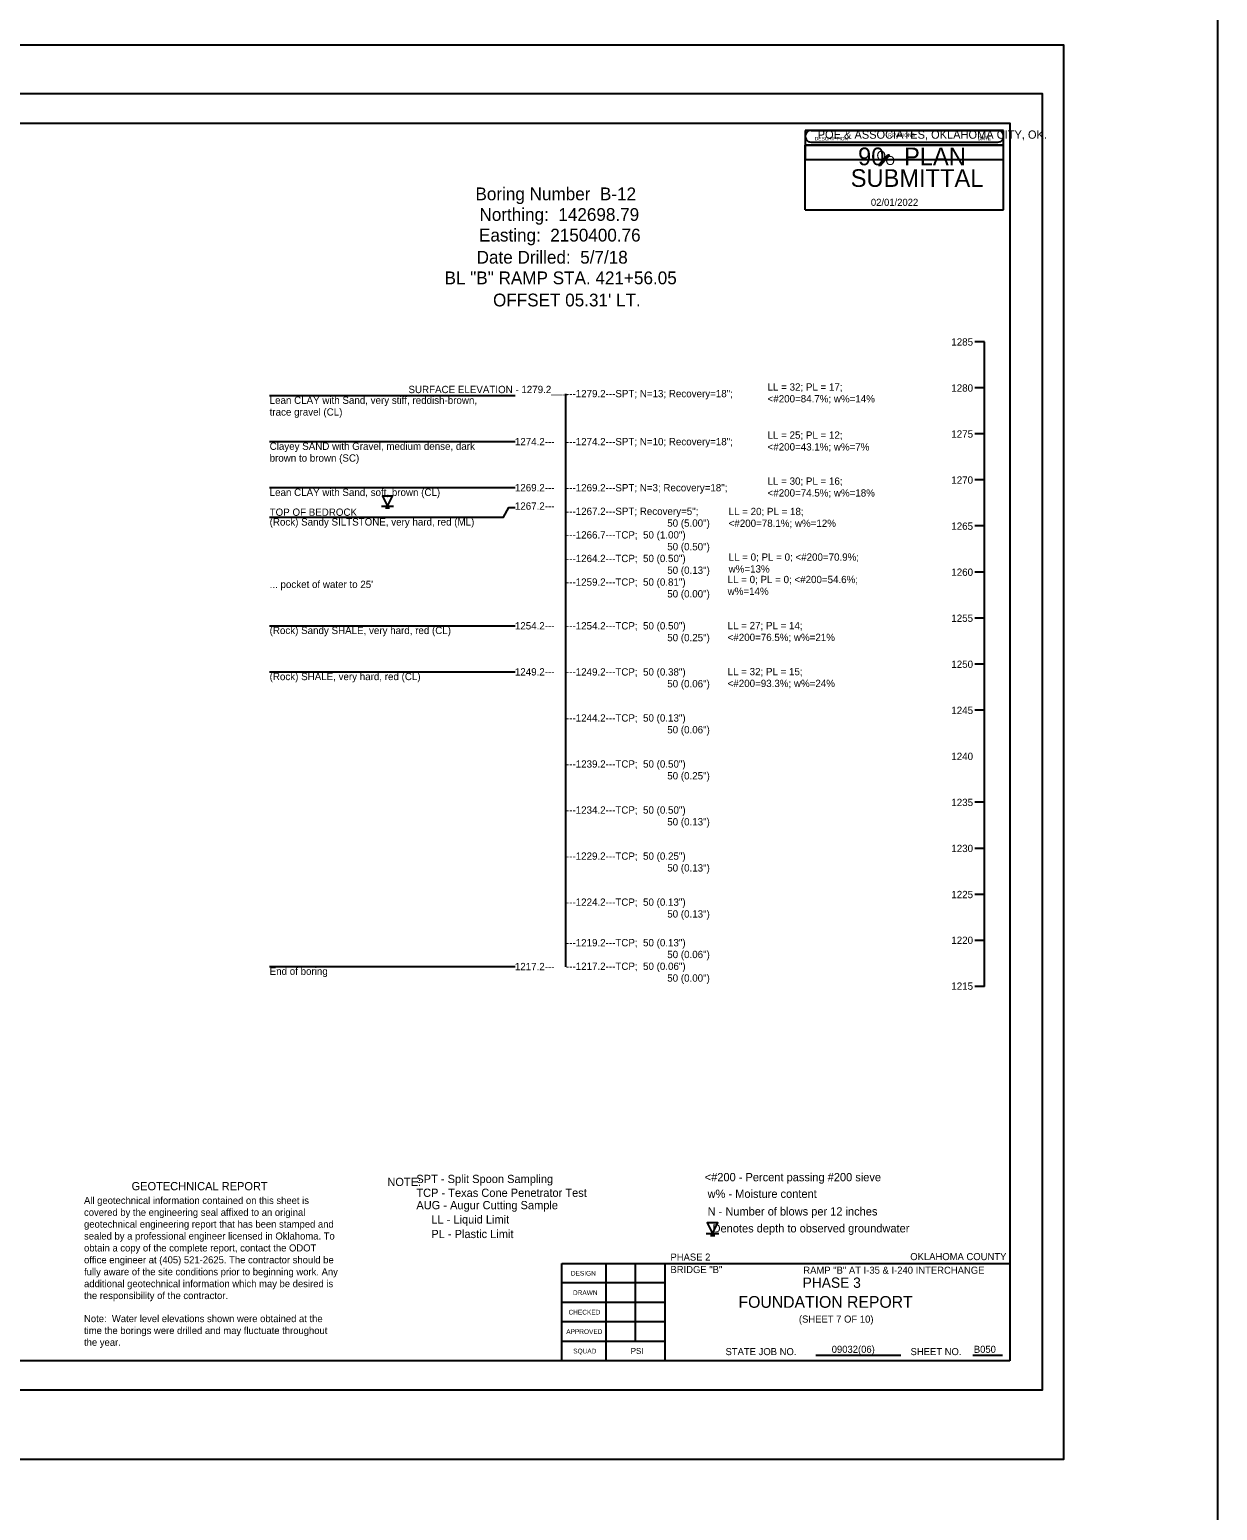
# Model space of a CAD drawing. Extents: x 2150162 to 2150245, y 143729 to 143865.
# Drawn here: x 2150225.08 to 2150245.24, y 143810.76 to 143835.89 of the extents above; entities that cross this region are included whole.
import ezdxf

# ---------------------------------------------------------------- set-up
doc = ezdxf.new("R2010")
doc.units = 0
for name, color, linetype in [('Default', 7, 'Continuous'), ('S', 7, 'Continuous'), ('SHT_Plot_Shape_Full', 7, 'Continuous'), ('SHT_Plot_Shape_Half', 7, 'Continuous'), ('SHT_Sheet_Border', 7, 'Continuous'), ('SHT_Stamp_90_Submit', 7, 'Continuous'), ('SHT_Stamp_Rev_Block', 7, 'Continuous'), ('SHT_Standard_Sheet_Lines', 7, 'Continuous'), ('SHT_Standard_Sheet_Txt', 7, 'Continuous'), ('T', 7, 'Continuous'), ('T-Title', 7, 'Continuous'), ('Text', 7, 'Continuous')]:
    doc.layers.add(name, color=color, linetype=linetype)

# ---------------------------------------------------------------- blocks, each defined once
blk = doc.blocks.new('DGRFC_WTLEV1')
at = {"layer": 'Default'}
for points in [[(-0.0127, 0), (0.0127, 0)], [(0, 0), (0.0106, 0.0212), (-0.0106, 0.0212), (0, 0)], [(-0.0042, -0.0042), (0.0042, -0.0042)]]:
    blk.add_lwpolyline(points, dxfattribs=at)

msp = doc.modelspace()

# ---------------------------------------------------------------- linework, layer by layer
at = {"layer": 'Default'}
msp.add_line((2150241.288, 143819.651), (2150241.288, 143830.588), dxfattribs=at)
for points in [[(2150241.288, 143830.59), (2150241.121, 143830.59)], [(2150229.155, 143829.677), (2150233.322, 143829.677)], [(2150234.174, 143829.705), (2150234.174, 143819.982)], [(2150241.288, 143829.808), (2150241.121, 143829.808)], [(2150229.155, 143828.895), (2150233.322, 143828.895)], [(2150234.174, 143828.845), (2150234.174, 143823.374)], [(2150241.288, 143829.027), (2150241.121, 143829.027)], [(2150241.288, 143829.027), (2150241.121, 143829.027)], [(2150229.155, 143828.114), (2150233.322, 143828.114)], [(2150241.288, 143828.246), (2150241.121, 143828.246)], [(2150229.155, 143827.611), (2150233.124, 143827.611), (2150233.213, 143827.777), (2150233.322, 143827.777)], [(2150241.288, 143827.465), (2150241.121, 143827.465)], [(2150241.288, 143826.683), (2150241.121, 143826.683)], [(2150241.288, 143825.902), (2150241.121, 143825.902)], [(2150229.155, 143825.77), (2150233.322, 143825.77)], [(2150241.288, 143825.121), (2150241.121, 143825.121)], [(2150229.155, 143824.989), (2150233.322, 143824.989)], [(2150241.288, 143824.34), (2150241.121, 143824.34)], [(2150241.288, 143822.776), (2150241.121, 143822.776)], [(2150241.288, 143821.994), (2150241.121, 143821.994)], [(2150241.288, 143821.213), (2150241.121, 143821.213)], [(2150241.288, 143820.432), (2150241.121, 143820.432)], [(2150229.155, 143819.989), (2150233.322, 143819.989)], [(2150241.288, 143819.651), (2150241.121, 143819.651)]]:
    msp.add_lwpolyline(points, dxfattribs=at)
at = {"layer": 'S'}
msp.add_lwpolyline([(2150203.404, 143865.061), (2150245.24, 143865.061), (2150245.24, 143729.315), (2150203.404, 143729.315)], close=True, dxfattribs=at)
at = {"layer": 'SHT_Plot_Shape_Full'}
msp.add_lwpolyline([(2150206.628, 143835.625), (2150242.628, 143835.625), (2150242.628, 143811.625), (2150206.628, 143811.625)], close=True, dxfattribs=at)
at = {"layer": 'SHT_Plot_Shape_Half'}
msp.add_lwpolyline([(2150208.265, 143834.8), (2150242.265, 143834.8), (2150242.265, 143812.8), (2150208.265, 143812.8)], close=True, dxfattribs=at)
at = {"layer": 'SHT_Sheet_Border'}
for p, q in [((2150234.115, 143813.3), (2150234.115, 143814.95)), ((2150234.115, 143814.95), (2150241.715, 143814.95)), ((2150235.865, 143813.3), (2150235.865, 143814.951))]:
    msp.add_line(p, q, dxfattribs=at)
msp.add_lwpolyline([(2150241.715, 143813.3), (2150210.215, 143813.3), (2150210.215, 143834.3), (2150241.715, 143834.3)], close=True, dxfattribs=at)
at = {"layer": 'SHT_Stamp_90_Submit'}
for p, q in [((2150238.346, 143834.176), (2150241.512, 143834.176)), ((2150238.246, 143833.926), (2150241.612, 143833.926)), ((2150238.246, 143832.827), (2150238.246, 143833.926)), ((2150238.346, 143833.976), (2150241.512, 143833.976)), ((2150241.612, 143832.827), (2150241.612, 143833.926)), ((2150239.489, 143833.588), (2150239.645, 143833.76)), ((2150239.507, 143833.588), (2150239.662, 143833.76)), ((2150239.512, 143833.588), (2150239.667, 143833.76)), ((2150239.52, 143833.588), (2150239.675, 143833.76)), ((2150239.645, 143833.76), (2150239.675, 143833.76)), ((2150239.489, 143833.588), (2150239.52, 143833.588)), ((2150238.246, 143832.827), (2150241.612, 143832.827))]:
    msp.add_line(p, q, dxfattribs=at)
for centre, start, end in [((2150238.346, 143834.076), 89.9952, 270), ((2150241.512, 143834.076), 270, 90.0048)]:
    msp.add_arc(centre, 0.1, start, end, dxfattribs=at)
at = {"layer": 'SHT_Stamp_Rev_Block'}
for p, q in [((2150238.246, 143834.176), (2150238.246, 143833.676)), ((2150241.612, 143834.176), (2150238.246, 143834.176)), ((2150241.612, 143833.676), (2150241.612, 143834.176)), ((2150241.612, 143833.926), (2150238.246, 143833.926)), ((2150241.612, 143833.676), (2150238.246, 143833.676))]:
    msp.add_line(p, q, dxfattribs=at)
at = {"layer": 'SHT_Standard_Sheet_Lines'}
for p, q in [((2150234.865, 143813.3), (2150234.865, 143814.951)), ((2150235.365, 143813.63), (2150235.365, 143814.951)), ((2150238.426, 143813.396), (2150239.866, 143813.396)), ((2150241.09, 143813.396), (2150241.593, 143813.396))]:
    msp.add_line(p, q, dxfattribs=at)
for points in [[(2150235.865, 143814.62), (2150234.115, 143814.62)], [(2150235.865, 143814.29), (2150234.115, 143814.29)], [(2150235.865, 143813.96), (2150234.115, 143813.96)], [(2150235.865, 143813.63), (2150234.115, 143813.63)]]:
    msp.add_lwpolyline(points, dxfattribs=at)

# ---------------------------------------------------------------- block references
at = {"layer": 'Default'}
for p, xscale, yscale in [((2150231.155, 143827.802), 7.873999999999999, 7.873999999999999), ((2150236.672, 143815.46), 8.503919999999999, 8.503919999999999)]:
    msp.add_blockref('DGRFC_WTLEV1', p, dxfattribs=dict(at, xscale=xscale, yscale=yscale))

# ---------------------------------------------------------------- texts
for s, height, p in [('Boring Number  B-12', 0.217, (2150232.648, 143832.99)), ('Northing:  142698.79', 0.217, (2150232.716, 143832.64)), ('Easting:  2150400.76', 0.217, (2150232.708, 143832.29)), ('Date Drilled:  5/7/18', 0.217, (2150232.668, 143831.915)), ('BL "B" RAMP STA. 421+56.05', 0.217, (2150232.124, 143831.565)), ("OFFSET 05.31' LT.", 0.217, (2150232.946, 143831.189)), ('1285', 0.124, (2150240.724, 143830.524)), ('SURFACE ELEVATION - 1279.2___', 0.124, (2150231.511, 143829.718)), ('LL = 32; PL = 17;', 0.124, (2150237.606, 143829.76)), ('1280', 0.124, (2150240.724, 143829.743)), ('Lean CLAY with Sand, very stiff, reddish-brown,', 0.124, (2150229.155, 143829.536)), ('---1279.2---SPT; N=13; Recovery=18";', 0.124, (2150234.184, 143829.648)), ('<#200=84.7%; w%=14%', 0.124, (2150237.606, 143829.56)), ('trace gravel (CL)', 0.124, (2150229.155, 143829.336)), ('1275', 0.124, (2150240.724, 143828.962)), ('Clayey SAND with Gravel, medium dense, dark', 0.124, (2150229.155, 143828.755)), ('1274.2---', 0.124, (2150233.317, 143828.833)), ('---1274.2---SPT; N=10; Recovery=18";', 0.124, (2150234.184, 143828.833)), ('<#200=43.1%; w%=7%', 0.124, (2150237.606, 143828.744)), ('LL = 25; PL = 12;', 0.124, (2150237.606, 143828.944)), ('brown to brown (SC)', 0.124, (2150229.155, 143828.555)), ('Lean CLAY with Sand, soft, brown (CL)', 0.124, (2150229.155, 143827.973)), ('1269.2---', 0.124, (2150233.317, 143828.052)), ('---1269.2---SPT; N=3; Recovery=18";', 0.124, (2150234.184, 143828.051)), ('<#200=74.5%; w%=18%', 0.124, (2150237.606, 143827.963)), ('LL = 30; PL = 16;', 0.124, (2150237.606, 143828.163)), ('1270', 0.124, (2150240.724, 143828.181)), ('1267.2---', 0.124, (2150233.317, 143827.74)), ('TOP OF BEDROCK', 0.124, (2150229.155, 143827.636)), ('(Rock) Sandy SILTSTONE, very hard, red (ML)', 0.124, (2150229.155, 143827.471)), ('---1267.2---SPT; Recovery=5";', 0.124, (2150234.184, 143827.651)), ('50 (5.00")', 0.124, (2150235.903, 143827.451)), ('<#200=78.1%; w%=12%', 0.124, (2150236.945, 143827.448)), ('LL = 20; PL = 18;', 0.124, (2150236.945, 143827.648)), ('---1266.7---TCP;  50 (1.00")', 0.124, (2150234.184, 143827.251)), ('1265', 0.124, (2150240.724, 143827.399)), ('50 (0.50")', 0.124, (2150235.903, 143827.051)), ('---1264.2---TCP;  50 (0.50")', 0.124, (2150234.184, 143826.851)), ('LL = 0; PL = 0; <#200=70.9%;', 0.124, (2150236.945, 143826.874)), ('---1259.2---TCP;  50 (0.81")', 0.124, (2150234.184, 143826.451)), ('50 (0.13")', 0.124, (2150235.903, 143826.651)), ('LL = 0; PL = 0; <#200=54.6%;', 0.124, (2150236.928, 143826.494)), ('w%=13%', 0.124, (2150236.945, 143826.674)), ('1260', 0.124, (2150240.724, 143826.618)), ("... pocket of water to 25'", 0.124, (2150229.155, 143826.411)), ('50 (0.00")', 0.124, (2150235.903, 143826.251)), ('w%=14%', 0.124, (2150236.928, 143826.294)), ('1254.2---', 0.124, (2150233.317, 143825.708)), ('---1254.2---TCP;  50 (0.50")', 0.124, (2150234.184, 143825.708)), ('LL = 27; PL = 14;', 0.124, (2150236.928, 143825.712)), ('1255', 0.124, (2150240.724, 143825.837)), ('(Rock) Sandy SHALE, very hard, red (CL)', 0.124, (2150229.155, 143825.63)), ('50 (0.25")', 0.124, (2150235.903, 143825.508)), ('<#200=76.5%; w%=21%', 0.124, (2150236.928, 143825.512)), ('---1249.2---TCP;  50 (0.38")', 0.124, (2150234.184, 143824.926)), ('LL = 32; PL = 15;', 0.124, (2150236.928, 143824.931)), ('1250', 0.124, (2150240.724, 143825.056)), ('(Rock) SHALE, very hard, red (CL)', 0.124, (2150229.155, 143824.848)), ('1249.2---', 0.124, (2150233.317, 143824.927)), ('50 (0.06")', 0.124, (2150235.903, 143824.726)), ('<#200=93.3%; w%=24%', 0.124, (2150236.928, 143824.731)), ('1245', 0.124, (2150240.724, 143824.274)), ('---1244.2---TCP;  50 (0.13")', 0.124, (2150234.184, 143824.145)), ('50 (0.06")', 0.124, (2150235.903, 143823.945)), ('1240', 0.124, (2150240.724, 143823.493)), ('---1239.2---TCP;  50 (0.50")', 0.124, (2150234.184, 143823.364)), ('50 (0.25")', 0.124, (2150235.903, 143823.164)), ('1235', 0.124, (2150240.724, 143822.712)), ('---1234.2---TCP;  50 (0.50")', 0.124, (2150234.184, 143822.583)), ('50 (0.13")', 0.124, (2150235.903, 143822.383)), ('1230', 0.124, (2150240.724, 143821.931)), ('---1229.2---TCP;  50 (0.25")', 0.124, (2150234.184, 143821.801)), ('50 (0.13")', 0.124, (2150235.903, 143821.601)), ('---1224.2---TCP;  50 (0.13")', 0.124, (2150234.184, 143821.02)), ('1225', 0.124, (2150240.724, 143821.149)), ('50 (0.13")', 0.124, (2150235.903, 143820.82)), ('---1219.2---TCP;  50 (0.13")', 0.124, (2150234.184, 143820.332)), ('1220', 0.124, (2150240.724, 143820.373)), ('1217.2---', 0.124, (2150233.317, 143819.927)), ('---1217.2---TCP;  50 (0.06")', 0.124, (2150234.184, 143819.932)), ('50 (0.06")', 0.124, (2150235.903, 143820.132)), ('End of boring', 0.124, (2150229.155, 143819.848)), ('50 (0.00")', 0.124, (2150235.903, 143819.732)), ('1215', 0.124, (2150240.724, 143819.595))]:
    msp.add_text(s, height=height, dxfattribs=at).set_placement(p)
at = {"layer": 'Defpoints'}
msp.add_text('PHASE 3', height=0.175, dxfattribs=at).set_placement((2150238.2, 143814.538))
at = {"layer": 'SHT_Stamp_90_Submit'}
for s, height, p in [('POE & ASSOCIATES, OKLAHOMA CITY, OK.', 0.14, (2150238.456, 143834.034)), ('90   PLAN', 0.3, (2150239.141, 143833.584)), ('O', 0.153, (2150239.455, 143833.673)), ('O', 0.153, (2150239.607, 143833.588)), ('SUBMITTAL', 0.3, (2150239.017, 143833.217)), ('02/01/2022', 0.12, (2150239.359, 143832.895))]:
    msp.add_text(s, height=height, dxfattribs=at).set_placement(p)
at = {"layer": 'SHT_Stamp_Rev_Block'}
for s, height, p in [('REVISIONS', 0.06, (2150239.654, 143834.064)), ('DESCRIPTION', 0.05999, (2150238.406, 143834.005)), ('DATE', 0.06, (2150241.175, 143834.009))]:
    msp.add_text(s, height=height, dxfattribs=at).set_placement(p)
at = {"layer": 'SHT_Standard_Sheet_Txt'}
for s, height, p in [('DESIGN', 0.08, (2150234.267, 143814.745)), ('DRAWN', 0.08, (2150234.303, 143814.415)), ('CHECKED', 0.08, (2150234.228, 143814.085)), ('APPROVED', 0.08, (2150234.189, 143813.755)), ('SQUAD', 0.08, (2150234.307, 143813.425)), ('STATE JOB NO.', 0.12, (2150236.892, 143813.396)), ('SHEET NO. ', 0.12, (2150240.032, 143813.396))]:
    msp.add_text(s, height=height, dxfattribs=at).set_placement(p)
at = {"layer": 'T'}
for s, height, p in [('PHASE 2', 0.12, (2150235.957, 143815)), ('OKLAHOMA COUNTY', 0.12, (2150240.027, 143815.008)), ('BRIDGE "B"', 0.12, (2150235.957, 143814.788)), ('RAMP "B" AT I-35 & I-240 INTERCHANGE', 0.12, (2150238.212, 143814.777)), ('(SHEET 7 OF 10)', 0.12, (2150238.137, 143813.948)), ('PSI', 0.1, (2150235.284, 143813.418)), ('09032(06)', 0.12, (2150238.694, 143813.435)), ('B050', 0.12, (2150241.106, 143813.435))]:
    msp.add_text(s, height=height, dxfattribs=at).set_placement(p)
at = {"layer": 'T-Title'}
msp.add_text('FOUNDATION REPORT', height=0.2, dxfattribs=at).set_placement((2150237.112, 143814.199))
at = {"layer": 'Text'}
for s, height, p in [('GEOTECHNICAL REPORT', 0.14, (2150226.812, 143816.193)), ('NOTE:', 0.14, (2150231.153, 143816.265)), ('    SPT - Split Spoon Sampling', 0.14, (2150231.437, 143816.316)), (' <#200 - Percent passing #200 sieve', 0.14, (2150236.487, 143816.346)), ('All geotechnical information contained on this sheet is ', 0.12, (2150226.005, 143815.961)), ('    AUG - Augur Cutting Sample', 0.14, (2150231.437, 143815.871)), ('    TCP - Texas Cone Penetrator Test', 0.14, (2150231.437, 143816.081)), ('w% - Moisture content', 0.14, (2150236.588, 143816.064)), ('covered by the engineering seal affixed to an original ', 0.12, (2150226.005, 143815.759)), (' LL - Liquid Limit', 0.14, (2150231.847, 143815.629)), ('N - Number of blows per 12 inches', 0.14, (2150236.588, 143815.765)), ('geotechnical engineering report that has been stamped and ', 0.12, (2150226.005, 143815.559)), (' PL - Plastic Limit', 0.14, (2150231.847, 143815.382)), ('    Denotes depth to observed groundwater', 0.14, (2150236.464, 143815.478)), ('sealed by a professional engineer licensed in Oklahoma. To ', 0.12, (2150226.005, 143815.357)), ('obtain a copy of the complete report, contact the ODOT ', 0.12, (2150226.005, 143815.155)), ('office engineer at (405) 521-2625. The contractor should be ', 0.12, (2150226.005, 143814.953)), ('fully aware of the site conditions prior to beginning work. Any ', 0.12, (2150226.005, 143814.751)), ('additional geotechnical information which may be desired is ', 0.12, (2150226.005, 143814.549)), ('the responsibility of the contractor.', 0.12, (2150226.005, 143814.347)), ('Note:  Water level elevations shown were obtained at the ', 0.12, (2150226.005, 143813.956)), ('time the borings were drilled and may fluctuate throughout ', 0.12, (2150226.005, 143813.754)), ('the year.', 0.12, (2150226.005, 143813.554))]:
    msp.add_text(s, height=height, dxfattribs=at).set_placement(p)

doc.saveas('drawing.dxf')
